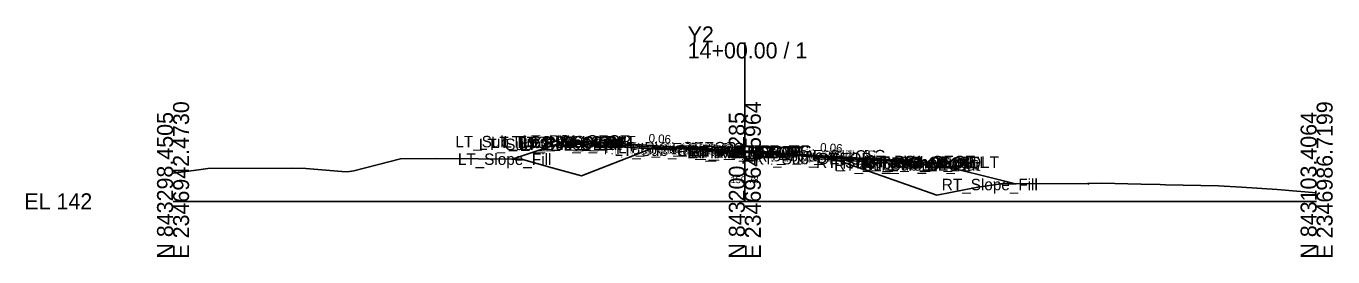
# Model space of a CAD drawing. Extents: x -26 to 2346977, y -10 to 843253.
# Drawn here: x -25.7 to 202.8, y 3490.3 to 3530.6 of the extents above; entities that cross this region are included whole.
import ezdxf

# ---------------------------------------------------------------- set-up
doc = ezdxf.new("R2010")
doc.units = 0
for name, color, linetype in [('Default', 7, 'Continuous'), ('Exist CMT Pavement', 7, 'Continuous'), ('Exist Cross Section Cell', 7, 'Continuous'), ('Exist XS Center Line Elevation Label', 7, 'Continuous'), ('Exist XS Ground Line', 7, 'Continuous'), ('Prop CMT Pvmt Course 1', 7, 'Continuous'), ('Prop CMT Pvmt Course 1 Wedge', 7, 'Continuous'), ('Prop CMT Pvmt Course 2', 7, 'Continuous'), ('Prop CMT Pvmt Course 2 Wedge', 7, 'Continuous'), ('Prop CMT Pvmt Course 3', 7, 'Continuous'), ('Prop CMT Pvmt Course 3 Wedge', 7, 'Continuous'), ('Prop CMT Pvmt Surface', 7, 'Continuous'), ('Prop CMT Pvmt Surface Shoulder', 7, 'Continuous'), ('Prop CMT Pvmt Wedge Surface 1', 7, 'Continuous'), ('Prop CMT Pvmt Wedge Surface 2', 7, 'Continuous'), ('Prop CMT Pvmt Wedge Surface 3', 7, 'Continuous'), ('Prop CMT Shld Paved Course 1', 7, 'Continuous'), ('Prop CMT Shld Paved Course 2', 7, 'Continuous'), ('Prop CMT Shld Paved Course 3', 7, 'Continuous'), ('Prop CMT Slope Grass', 7, 'Continuous'), ('Prop CMT Subgrade Earthwork', 7, 'Continuous'), ('Prop Road Sect_ Recs - UUC (pattern)', 7, 'Continuous'), ('Prop XS Earthwork Shape', 7, 'Continuous'), ('Prop XS SE Text', 7, 'Continuous'), ('Prop XS Side Slope Text', 7, 'Continuous'), ('Scratch_Level_2', 7, 'Continuous')]:
    doc.layers.add(name, color=color, linetype=linetype)

msp = doc.modelspace()

# ---------------------------------------------------------------- linework, layer by layer
at = {"layer": 'Exist CMT Pavement'}
for p, q in [((87.97, 3509.22), (87.98, 3509.22)), ((87.98, 3509.22), (88.5, 3509.21)), ((88.5, 3509.21), (90, 3509.18)), ((90, 3509.18), (90.4, 3509.17)), ((90.4, 3509.17), (92.31, 3509.1)), ((92.31, 3509.1), (92.54, 3509.09)), ((92.54, 3509.09), (92.58, 3509.09)), ((92.58, 3509.09), (92.66, 3509.09)), ((92.66, 3509.09), (95.15, 3508.99)), ((95.15, 3508.99), (96, 3508.95)), ((96, 3508.95), (97.7, 3508.88)), ((97.7, 3508.88), (100, 3508.78)), ((100, 3508.78), (100.21, 3508.78)), ((100.21, 3508.78), (100.58, 3508.76)), ((100.58, 3508.76), (100.63, 3508.76)), ((100.63, 3508.76), (101.91, 3508.67)), ((101.91, 3508.67), (102.8, 3508.61)), ((102.8, 3508.61), (102.95, 3508.61)), ((102.95, 3508.61), (103.59, 3508.57)), ((103.59, 3508.57), (105.35, 3508.46)), ((105.35, 3508.46), (107.09, 3508.35)), ((107.09, 3508.35), (107.9, 3508.29)), ((107.9, 3508.29), (109.18, 3508.2)), ((109.18, 3508.2), (110.49, 3508.11)), ((110.49, 3508.11), (111.01, 3508.08)), ((111.01, 3508.08), (111.73, 3508.02)), ((111.73, 3508.02), (112.07, 3508)), ((112.07, 3508), (112.21, 3507.99))]:
    msp.add_line(p, q, dxfattribs=at)
at = {"layer": 'Exist Cross Section Cell'}
for p, q in [((100, 3500), (100, 3527.77)), ((0, 3500), (100, 3500)), ((100, 3500), (200, 3500))]:
    msp.add_line(p, q, dxfattribs=at)
at = {"layer": 'Exist XS Ground Line'}
msp.add_lwpolyline([(0, 3504.94), (4.43, 3505.51), (6.1, 3505.76), (20.79, 3505.77), (23.22, 3505.76), (29.51, 3505.23), (30.43, 3505.15), (31.62, 3505.36), (39.8, 3507.42), (45.92, 3507.49), (60.96, 3507.36), (66.32, 3505.86), (71.46, 3504.47), (82.81, 3508.86), (83.88, 3509.26), (84.25, 3509.24), (87.59, 3509.23), (87.97, 3509.22), (88.5, 3509.21), (90, 3509.18), (90.4, 3509.17), (92.66, 3509.09), (95.15, 3508.99), (96, 3508.95), (97.7, 3508.88), (100.21, 3508.78), (100.63, 3508.76), (101.91, 3508.67), (102.95, 3508.61), (103.59, 3508.57), (105.35, 3508.46), (107.09, 3508.35), (107.9, 3508.29), (109.18, 3508.2), (110.49, 3508.11), (111.01, 3508.08), (111.73, 3508.02), (112.21, 3507.99), (113.75, 3507.72), (115.48, 3507.43), (118.64, 3506.35), (133.56, 3501.1), (140.72, 3502.45), (144.77, 3503.05), (159.9, 3503.11), (162.36, 3503.2), (169.29, 3503), (172.61, 3502.92), (173.58, 3502.9), (182.86, 3502.73), (186.85, 3502.48), (193.12, 3502.06), (200, 3501.46)], dxfattribs=at)
at = {"layer": 'Prop CMT Pvmt Course 1'}
for p, q in [((100, 3508.78), (70.38, 3510.56)), ((70.38, 3510.56), (70.38, 3510.31)), ((70.38, 3510.31), (87.97, 3509.26)), ((87.97, 3509.26), (87.97, 3509.38)), ((87.97, 3509.38), (100, 3508.66)), ((100, 3508.53), (100, 3508.78)), ((100, 3508.78), (130.38, 3506.96)), ((100, 3508.53), (100, 3508.78)), ((100, 3508.66), (100, 3508.53)), ((112.21, 3507.93), (100, 3508.66)), ((100, 3508.66), (100, 3508.53)), ((100, 3508.53), (100, 3508.53)), ((100, 3508.53), (100, 3508.53)), ((112.21, 3507.8), (112.21, 3507.93)), ((130.38, 3506.71), (112.21, 3507.8)), ((130.38, 3506.96), (130.38, 3506.71))]:
    msp.add_line(p, q, dxfattribs=at)
at = {"layer": 'Prop CMT Pvmt Course 1 Wedge'}
for p, q in [((87.97, 3509.38), (87.97, 3509.38)), ((87.97, 3509.38), (87.98, 3509.38)), ((87.97, 3509.26), (87.97, 3509.38)), ((87.98, 3509.26), (87.97, 3509.26)), ((87.97, 3509.26), (87.97, 3509.26)), ((87.98, 3509.38), (88.5, 3509.35)), ((88.5, 3509.22), (87.98, 3509.26)), ((88.5, 3509.35), (90, 3509.26)), ((88.79, 3509.21), (88.5, 3509.22)), ((90, 3509.18), (88.79, 3509.21)), ((90, 3509.26), (90.4, 3509.24)), ((90.4, 3509.17), (90, 3509.18)), ((90.4, 3509.24), (92.31, 3509.12)), ((92.31, 3509.1), (90.4, 3509.17)), ((92.31, 3509.12), (92.54, 3509.11)), ((92.54, 3509.09), (92.31, 3509.1)), ((92.54, 3509.11), (92.58, 3509.1)), ((92.58, 3509.09), (92.54, 3509.09)), ((92.58, 3509.1), (92.66, 3509.1)), ((92.66, 3509.09), (92.58, 3509.09)), ((92.66, 3509.1), (93.24, 3509.07)), ((93.24, 3509.07), (92.66, 3509.09))]:
    msp.add_line(p, q, dxfattribs=at)
at = {"layer": 'Prop CMT Pvmt Course 2'}
for p, q in [((70.38, 3510.31), (87.97, 3509.26)), ((87.97, 3509.26), (70.38, 3510.31)), ((70.38, 3510.31), (70.38, 3510.31)), ((87.97, 3509.26), (87.97, 3509.26)), ((130.38, 3506.71), (112.21, 3507.8)), ((112.21, 3507.8), (112.21, 3507.8)), ((112.21, 3507.8), (130.38, 3506.71)), ((130.38, 3506.71), (130.38, 3506.71))]:
    msp.add_line(p, q, dxfattribs=at)
at = {"layer": 'Prop CMT Pvmt Course 2 Wedge'}
for p, q in [((87.97, 3509.26), (87.97, 3509.26)), ((87.97, 3509.26), (87.98, 3509.26)), ((87.97, 3509.22), (87.97, 3509.26)), ((87.98, 3509.22), (87.97, 3509.22)), ((87.97, 3509.22), (87.97, 3509.22)), ((87.98, 3509.26), (88.5, 3509.22)), ((88.5, 3509.21), (87.98, 3509.22)), ((88.5, 3509.22), (88.79, 3509.21)), ((88.79, 3509.21), (88.5, 3509.21))]:
    msp.add_line(p, q, dxfattribs=at)
at = {"layer": 'Prop CMT Pvmt Course 3'}
for p, q in [((87.97, 3509.26), (70.38, 3510.31)), ((70.38, 3510.31), (70.38, 3509.98)), ((70.38, 3509.98), (87.97, 3508.92)), ((87.97, 3508.92), (87.97, 3509.26)), ((112.21, 3507.8), (130.38, 3506.71)), ((112.21, 3507.47), (112.21, 3507.8)), ((130.38, 3506.38), (112.21, 3507.47)), ((130.38, 3506.71), (130.38, 3506.38))]:
    msp.add_line(p, q, dxfattribs=at)
at = {"layer": 'Prop CMT Pvmt Course 3 Wedge'}
for p, q in [((87.97, 3509.26), (87.97, 3509.26)), ((87.97, 3509.26), (87.98, 3509.26)), ((87.97, 3509.22), (87.97, 3509.26)), ((87.98, 3509.22), (87.97, 3509.22)), ((87.97, 3509.22), (87.97, 3509.22)), ((87.98, 3509.26), (88.5, 3509.22)), ((88.5, 3509.21), (87.98, 3509.22)), ((88.5, 3509.22), (88.79, 3509.21)), ((88.79, 3509.21), (88.5, 3509.21))]:
    msp.add_line(p, q, dxfattribs=at)
at = {"layer": 'Prop CMT Pvmt Surface'}
for q in [(70.38, 3510.56), (130.38, 3506.96)]:
    msp.add_line((100, 3508.78), q, dxfattribs=at)
at = {"layer": 'Prop CMT Pvmt Surface Shoulder'}
for p, q in [((70.38, 3510.56), (70.38, 3510.56)), ((130.38, 3506.96), (130.38, 3506.96))]:
    msp.add_line(p, q, dxfattribs=at)
at = {"layer": 'Prop CMT Pvmt Wedge Surface 1'}
for p, q in [((70.38, 3510.31), (70.38, 3510.56)), ((87.97, 3509.26), (70.38, 3510.31)), ((100, 3508.66), (87.97, 3509.38)), ((87.97, 3509.38), (87.97, 3509.26)), ((100, 3508.66), (112.21, 3507.93)), ((112.21, 3507.93), (112.21, 3507.8)), ((112.21, 3507.8), (130.38, 3506.71)), ((130.38, 3506.71), (130.38, 3506.96))]:
    msp.add_line(p, q, dxfattribs=at)
at = {"layer": 'Prop CMT Pvmt Wedge Surface 2'}
for p, q in [((70.38, 3510.31), (70.38, 3510.56)), ((100, 3508.53), (70.38, 3510.31)), ((100, 3508.53), (130.38, 3506.71)), ((130.38, 3506.71), (130.38, 3506.96))]:
    msp.add_line(p, q, dxfattribs=at)
at = {"layer": 'Prop CMT Pvmt Wedge Surface 3'}
for p, q in [((70.38, 3510.31), (70.38, 3510.56)), ((100, 3508.53), (70.38, 3510.31)), ((100, 3508.53), (130.38, 3506.71)), ((130.38, 3506.71), (130.38, 3506.96))]:
    msp.add_line(p, q, dxfattribs=at)
at = {"layer": 'Prop CMT Shld Paved Course 1'}
for p, q in [((70.38, 3510.56), (70.12, 3510.31)), ((70.12, 3510.31), (70.38, 3510.31)), ((70.38, 3510.56), (70.38, 3510.56)), ((70.38, 3510.31), (70.38, 3510.56)), ((130.38, 3506.96), (130.38, 3506.96)), ((130.38, 3506.96), (130.63, 3506.71)), ((130.38, 3506.71), (130.38, 3506.96)), ((130.63, 3506.71), (130.38, 3506.71))]:
    msp.add_line(p, q, dxfattribs=at)
at = {"layer": 'Prop CMT Shld Paved Course 2'}
for p, q in [((70.38, 3510.31), (70.12, 3510.31)), ((70.12, 3510.31), (70.12, 3510.31)), ((70.12, 3510.31), (70.38, 3510.31)), ((70.38, 3510.31), (70.38, 3510.31)), ((130.38, 3506.71), (130.63, 3506.71)), ((130.63, 3506.71), (130.38, 3506.71)), ((130.38, 3506.71), (130.38, 3506.71)), ((130.63, 3506.71), (130.63, 3506.71))]:
    msp.add_line(p, q, dxfattribs=at)
at = {"layer": 'Prop CMT Shld Paved Course 3'}
for p, q in [((69.62, 3510.3), (69.28, 3509.96)), ((70.12, 3510.31), (69.62, 3510.3)), ((70.38, 3510.31), (70.12, 3510.31)), ((70.38, 3509.98), (70.38, 3510.31)), ((69.28, 3509.96), (70.38, 3509.98)), ((130.38, 3506.71), (130.63, 3506.71)), ((130.38, 3506.38), (130.38, 3506.71)), ((131.47, 3506.36), (130.38, 3506.38)), ((130.63, 3506.71), (131.13, 3506.7)), ((131.13, 3506.7), (131.47, 3506.36))]:
    msp.add_line(p, q, dxfattribs=at)
at = {"layer": 'Prop CMT Slope Grass'}
for p, q in [((68.38, 3510.4), (59.29, 3507.37)), ((70.38, 3510.56), (68.38, 3510.4)), ((130.38, 3506.96), (132.38, 3506.8)), ((132.38, 3506.8), (147.33, 3503.06))]:
    msp.add_line(p, q, dxfattribs=at)
at = {"layer": 'Prop CMT Subgrade Earthwork'}
for p, q in [((69.28, 3509.96), (68.8, 3510.44)), ((70.38, 3509.98), (69.28, 3509.96)), ((87.97, 3508.92), (70.38, 3509.98)), ((87.97, 3508.92), (87.97, 3509.22)), ((112.21, 3507.47), (112.21, 3507.99)), ((112.21, 3507.47), (130.38, 3506.38)), ((130.38, 3506.38), (131.47, 3506.36)), ((131.47, 3506.36), (131.95, 3506.84))]:
    msp.add_line(p, q, dxfattribs=at)
at = {"layer": 'Prop Road Sect_ Recs - UUC (pattern)'}
for p, q in [((147.42, 3503.04), (147.45, 3503.06)), ((147.42, 3503.04), (147.45, 3503.06)), ((147.42, 3503.04), (147.45, 3503.06)), ((160.07, 3502.96), (160.24, 3503.13)), ((160.07, 3502.96), (160.24, 3503.13)), ((160.07, 3502.96), (160.24, 3503.13))]:
    msp.add_line(p, q, dxfattribs=at)
at = {"layer": 'Prop XS Earthwork Shape'}
for points in [[(70.38, 3509.98), (69.28, 3509.96), (68.8, 3510.44), (68.38, 3510.4), (59.29, 3507.37), (60.96, 3507.36), (66.32, 3505.86), (71.46, 3504.47), (82.81, 3508.86), (83.68, 3509.18)], [(83.68, 3509.18), (83.88, 3509.26), (84.25, 3509.24), (87.59, 3509.23), (87.97, 3509.22), (87.97, 3508.92)], [(92.58, 3509.09), (92.66, 3509.09), (92.31, 3509.1), (92.54, 3509.09)], [(100, 3508.78), (100.21, 3508.78), (100.58, 3508.76), (100.63, 3508.76), (101.91, 3508.67), (102.42, 3508.64)], [(100.21, 3508.78), (100.58, 3508.76), (100.63, 3508.76)], [(102.42, 3508.64), (102.52, 3508.63), (101.91, 3508.67)], [(102.42, 3508.64), (102.52, 3508.63), (102.95, 3508.61), (102.8, 3508.61)], [(111.73, 3508.02), (112.07, 3508), (112.21, 3507.99)], [(112.21, 3507.99), (113.75, 3507.72), (115.48, 3507.43), (116.03, 3507.24), (112.21, 3507.47)], [(131.95, 3506.84), (132.38, 3506.8), (147.33, 3503.06), (144.77, 3503.05), (140.72, 3502.45), (133.56, 3501.1), (118.64, 3506.35), (116.03, 3507.24), (130.38, 3506.38), (131.47, 3506.36)]]:
    msp.add_lwpolyline(points, close=True, dxfattribs=at)

# ---------------------------------------------------------------- texts
at = {"layer": 'Default'}
msp.add_text('-', height=0.0001, dxfattribs=at).set_placement((0, 3500))
at = {"layer": 'Exist Cross Section Cell'}
for s, p in [('Y2', (90, 3527.77)), ('14+00.00 / 1', (90, 3524.97)), ('EL 142', (-26, 3498.6))]:
    msp.add_text(s, height=2.8, dxfattribs=at).set_placement(p)
for s, p in [('E 2346942.4730', (2.8, 3490)), ('E 2346964.5964', (102.8, 3490)), ('E 2346986.7199', (202.8, 3490)), ('N 843298.4505', (0, 3490)), ('N 843200.9285', (100, 3490)), ('N 843103.4064', (200, 3490))]:
    msp.add_text(s, height=2.8, rotation=90, dxfattribs=at).set_placement(p)
at = {"layer": 'Exist XS Center Line Elevation Label'}
msp.add_text('150.78', height=1.2, dxfattribs=at).set_placement((97.51, 3503.18))
at = {"layer": 'Prop XS SE Text'}
for s, rotation, p in [('0.06', 356.5664, (83.13, 3510.31)), ('0.06', 356.5664, (113.13, 3508.71)), ('4:1', 345.9638, (138.54, 3505.9))]:
    msp.add_text(s, height=1.5, rotation=rotation, dxfattribs=at).set_placement(p)
at = {"layer": 'Prop XS Side Slope Text'}
msp.add_text('3:1', height=1.5, rotation=18.4332, dxfattribs=at).set_placement((63.35, 3509.14))
at = {"layer": 'Scratch_Level_2'}
for s, p in [('LT_Sub_Trench_Out_DLT', (49.37, 3509.44)), ('LT_Sub_Trench_Out', (53.49, 3508.96)), ('LT_PS3_Shelf_Out', (55.6, 3509.3)), ('LT_GS_OS_CTL', (57.75, 3509.4)), ('LT_PS3_OEOP', (60.36, 3509.31)), ('LT_PS2_OEOP', (60.36, 3509.31)), ('LT_Sub_OEOT', (60.45, 3508.98)), ('LT_PV3_OEOT', (60.55, 3509.31)), ('LT_PV2_OEOT', (60.55, 3509.31)), ('LT_PV1_OEOT', (61.12, 3509.56)), ('LT_PS1_OEOP', (61.18, 3509.56)), ('LT_Sub Tie Out', (75.31, 3508.22)), ('LT_PV2_OEEOP', (77.27, 3508.26)), ('LT_PV3_OEEOP', (77.27, 3508.26)), ('LT_PV1_OEEOP', (77.84, 3508.38)), ('LT_Slope_Fill', (49.81, 3506.37)), ('LT_PV_OEEOP_EG', (75.51, 3508.22)), ('LT_Sub_OEEOP', (77.18, 3507.92)), ('RT_PV_IEEOP_EG', (88.14, 3507.78)), ('LT_PV_IEEOP_EG', (88.19, 3507.78)), ('RT_PV2_IEEOP', (89.91, 3507.53)), ('RT_PV3_IEEOP', (89.91, 3507.53)), ('LT_PV2_IEEOP', (89.95, 3507.53)), ('LT_PV3_IEEOP', (89.95, 3507.53)), ('RT_PV1_IEEOP', (90.47, 3507.66)), ('LT_PV1_IEEOP', (90.52, 3507.66)), ('PV2_PGL', (93.91, 3507.53)), ('PV1_PGL', (94.47, 3507.78)), ('RT_Sub Tie Out', (99.5, 3506.99)), ('RT_PV_OEEOP_EG', (99.71, 3506.99)), ('RT_Sub_OEEOP', (101.38, 3506.47)), ('RT_PV2_OEEOP', (101.47, 3506.8)), ('RT_PV3_OEEOP', (101.47, 3506.8)), ('RT_PV1_OEEOP', (102.04, 3506.93)), ('RT_PV1_OEOT', (121.07, 3505.96)), ('RT_PS1_OEOP', (121.13, 3505.96)), ('RT_Sub_Trench_Out_DLT', (112.47, 3505.84)), ('RT_Sub_Trench_Out', (115.63, 3505.36)), ('RT_PS3_Shelf_Out', (117.07, 3505.7)), ('RT_Sub_OEOT', (120.41, 3505.38)), ('RT_PV3_OEOT', (120.5, 3505.71)), ('RT_PV2_OEOT', (120.5, 3505.71)), ('RT_PS3_OEOP', (120.82, 3505.71)), ('RT_PS2_OEOP', (120.82, 3505.71)), ('RT_GS_OS_CTL', (121.7, 3505.8)), ('RT_Slope_Fill', (134.45, 3501.94))]:
    msp.add_text(s, height=2, dxfattribs=at).set_placement(p)

doc.saveas('drawing.dxf')
